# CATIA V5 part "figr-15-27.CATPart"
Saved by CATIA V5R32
Part number: Part1
Bounding box of the stored display mesh (mm): x -61.282 to 61.282, y -26.72 to 26.72, z 0 to 0.75
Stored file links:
  D:\PROJECTS\Project 2022\CATIA V5 6R 2022\Resources\Part Files\c15_catia_v5_6r2022_prt\figr-15-27.CATPart
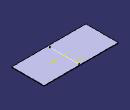
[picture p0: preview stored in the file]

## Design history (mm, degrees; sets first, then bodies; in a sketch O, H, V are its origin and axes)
SheetMetalParameters1: Thickness 0.75, BendRadius 1, KFactor 0.356492 {= log(min(100,max(20*SheetMetalParameters1.BendRadius,SheetMetalParameters1.Thickness)/SheetMetalParameters1.Thickness))/log(100)/2}, ReliefRadialLength 1, ReliefAxialLength 2, MinimumBendRadius 0
Body1 (main body)
  Sketch1 on xy-plane, origin (0, 0, 0), H (1, 0, 0), V (0, 1, 0)
    line L1 (61.282, 26.7197) -> (61.282, -26.7197)
    line L2 (61.282, -26.7197) -> (-61.282, -26.7197)
    line L3 (-61.282, -26.7197) -> (-61.282, 26.7197)
    line L4 (-61.282, 26.7197) -> (61.282, 26.7197)
    vertical: L1 V, L3 V
    horizontal: L2 H, L4 H
    equidistance: L1 L3 O, L2 L4 O
  Wall1: Thickness 0.75, Profile Sketch1
  Sketch2 on face of Wall1, origin (0, 0, 0.75), H (1, 0, 0), V (0, 1, 0)
    line L1 (1.9015, 25.4615) -> (1.9015, -22.9675)
    vertical: L1 V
